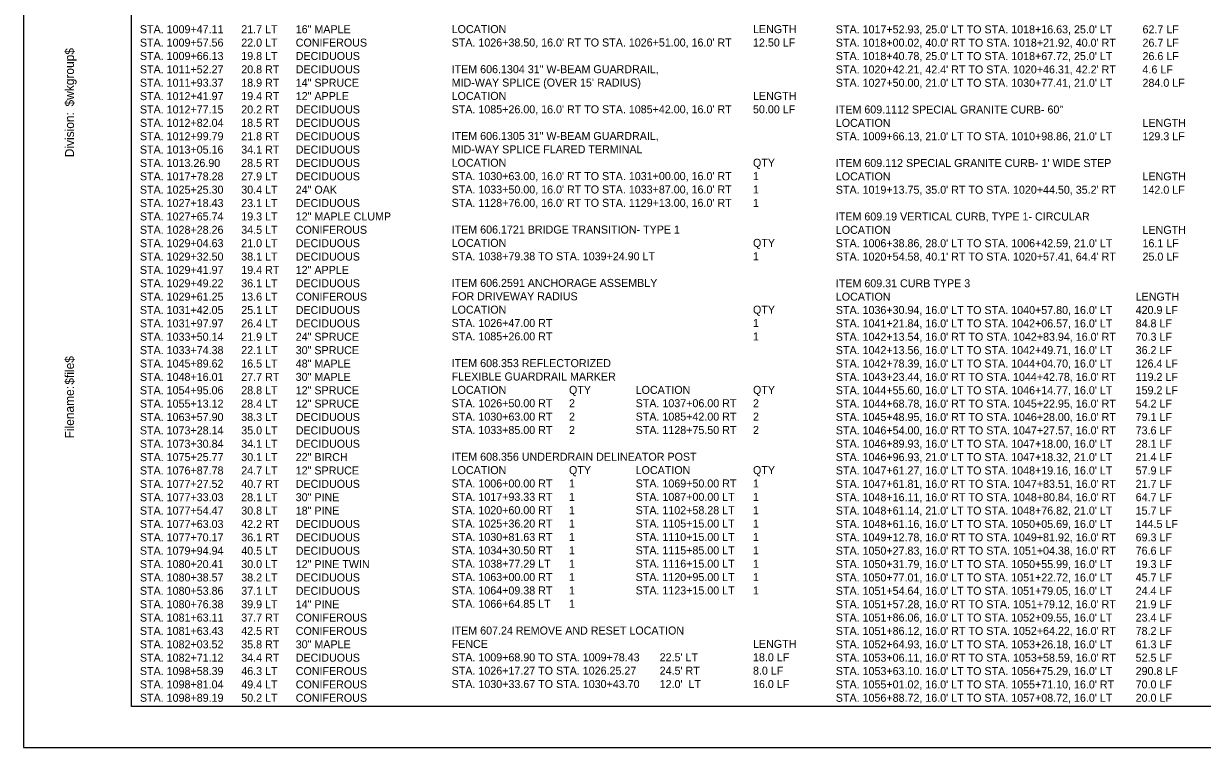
# Model space of a CAD drawing. Extents: x -831 to 3331, y -1004 to 250.
# Drawn here: x 102.6 to 544.6, y -965.1 to -693.8 of the extents above; entities that cross this region are included whole.
import ezdxf

# ---------------------------------------------------------------- set-up
doc = ezdxf.new("R2010")
doc.units = 0
for name, color, linetype in [('BORDER', 7, 'Continuous'), ('Default', 7, 'Continuous'), ('PLOT BOUNDARY', 7, 'Continuous')]:
    doc.layers.add(name, color=color, linetype=linetype)

msp = doc.modelspace()

# ---------------------------------------------------------------- linework, layer by layer
at = {"layer": 'BORDER'}
msp.add_lwpolyline([(143.03, -424.76), (943.03, -424.76), (943.03, -949.76), (143.03, -949.76)], close=True, dxfattribs=at)
at = {"layer": 'PLOT BOUNDARY'}
msp.add_lwpolyline([(102.57, -965.05), (952.57, -965.05), (952.57, -415.05), (102.57, -415.05)], close=True, dxfattribs=at)

# ---------------------------------------------------------------- texts
at = {"layer": 'BORDER'}
for s, p in [('$wkgroup$', (121.46, -724.91)), ('Division:', (121.46, -743.93)), ('$file$', (121.46, -829.13)), ('Filename:', (121.46, -849.27))]:
    msp.add_text(s, height=3.348, rotation=90, dxfattribs=at).set_placement(p)
at = {"layer": 'Default'}
for s, p in [('STA. 1009+47.11', (146.19, -697.46)), ('21.7 LT', (184.19, -697.46)), ('16" MAPLE', (204.62, -697.46)), ('LOCATION', (263.08, -697.42)), ('LENGTH', (376.08, -697.42)), ("STA. 1017+52.93, 25.0' LT TO STA. 1018+16.63, 25.0' LT", (407.14, -697.5)), ('62.7 LF', (522.14, -697.5)), ('STA. 1009+57.56', (146.19, -702.47)), ('22.0 LT', (184.19, -702.47)), ('CONIFEROUS', (204.62, -702.47)), ("STA. 1026+38.50, 16.0' RT TO STA. 1026+51.00, 16.0' RT", (263.08, -702.43)), ('12.50 LF', (376.08, -702.43)), ("STA. 1018+00.02, 40.0' RT TO STA. 1018+21.92, 40.0' RT", (407.14, -702.51)), ('26.7 LF', (522.14, -702.51)), ('STA. 1009+66.13', (146.19, -707.48)), ('19.8 LT', (184.19, -707.48)), ('DECIDUOUS', (204.62, -707.48)), ("STA. 1018+40.78, 25.0' LT TO STA. 1018+67.72, 25.0' LT ", (407.14, -707.52)), ('26.6 LF', (522.14, -707.52)), ('STA. 1011+52.27', (146.19, -712.49)), ('20.8 RT', (184.19, -712.49)), ('DECIDUOUS', (204.62, -712.49)), ('ITEM 606.1304 31" W-BEAM GUARDRAIL, ', (263.08, -712.43)), ("STA. 1020+42.21, 42.4' RT TO STA. 1020+46.31, 42.2' RT", (407.14, -712.53)), ('4.6 LF', (522.14, -712.53)), ('STA. 1011+93.37', (146.19, -717.5)), ('18.9 RT', (184.19, -717.5)), ('14" SPRUCE', (204.62, -717.5)), ("MID-WAY SPLICE (OVER 15' RADIUS)", (263.08, -717.44)), ("STA. 1027+50.00, 21.0' LT TO STA. 1030+77.41, 21.0' LT", (407.14, -717.54)), ('284.0 LF', (522.14, -717.54)), ('STA. 1012+41.97', (146.19, -722.51)), ('19.4 RT', (184.19, -722.51)), ('12" APPLE', (204.62, -722.51)), ('LOCATION', (263.08, -722.45)), ('LENGTH', (376.08, -722.45)), ('STA. 1012+77.15', (146.19, -727.52)), ('20.2 RT', (184.19, -727.52)), ('DECIDUOUS', (204.62, -727.52)), ("STA. 1085+26.00, 16.0' RT TO STA. 1085+42.00, 16.0' RT", (263.08, -727.46)), ('50.00 LF', (376.08, -727.46)), ('ITEM 609.1112 SPECIAL GRANITE CURB- 60"', (407.14, -727.54)), ('STA. 1012+82.04', (146.19, -732.53)), ('18.5 RT', (184.19, -732.53)), ('DECIDUOUS', (204.62, -732.53)), ('LOCATION', (407.14, -732.55)), ('LENGTH', (522.14, -732.55)), ('STA. 1012+99.79', (146.19, -737.54)), ('21.8 RT', (184.19, -737.54)), ('DECIDUOUS', (204.62, -737.54)), ('ITEM 606.1305 31" W-BEAM GUARDRAIL, ', (263.08, -737.46)), ("STA. 1009+66.13, 21.0' LT TO STA. 1010+98.86, 21.0' LT", (407.14, -737.56)), ('129.3 LF', (522.14, -737.56)), ('STA. 1013+05.16', (146.19, -742.55)), ('34.1 RT', (184.19, -742.55)), ('DECIDUOUS', (204.62, -742.55)), ('MID-WAY SPLICE FLARED TERMINAL', (263.08, -742.47)), ('STA. 1013.26.90', (146.19, -747.56)), ('28.5 RT', (184.19, -747.56)), ('DECIDUOUS', (204.62, -747.56)), ('LOCATION', (263.08, -747.48)), ('QTY', (376.08, -747.48)), ("ITEM 609.112 SPECIAL GRANITE CURB- 1' WIDE STEP", (407.14, -747.58)), ('STA. 1017+78.28', (146.19, -752.57)), ('27.9 LT', (184.19, -752.57)), ('DECIDUOUS', (204.62, -752.57)), ("STA. 1030+63.00, 16.0' RT TO STA. 1031+00.00, 16.0' RT", (263.08, -752.49)), ('1', (376.08, -752.49)), ('LOCATION', (407.14, -752.59)), ('LENGTH', (522.14, -752.59)), ('STA. 1025+25.30', (146.19, -757.58)), ('30.4 LT', (184.19, -757.58)), ('24" OAK', (204.62, -757.58)), ("STA. 1033+50.00, 16.0' RT TO STA. 1033+87.00, 16.0' RT", (263.08, -757.5)), ('1', (376.08, -757.5)), ("STA. 1019+13.75, 35.0' RT TO STA. 1020+44.50, 35.2' RT", (407.14, -757.6)), ('142.0 LF', (522.14, -757.6)), ('STA. 1027+18.43', (146.19, -762.59)), ('23.1 LT', (184.19, -762.59)), ('DECIDUOUS', (204.62, -762.59)), ("STA. 1128+76.00, 16.0' RT TO STA. 1129+13.00, 16.0' RT", (263.08, -762.51)), ('1', (376.08, -762.51)), ('STA. 1027+65.74', (146.19, -767.6)), ('19.3 LT', (184.19, -767.6)), ('12" MAPLE CLUMP', (204.62, -767.6)), ('ITEM 609.19 VERTICAL CURB, TYPE 1- CIRCULAR', (407.14, -767.62)), ('STA. 1028+28.26', (146.19, -772.61)), ('34.5 LT', (184.19, -772.61)), ('CONIFEROUS', (204.62, -772.61)), ('ITEM 606.1721 BRIDGE TRANSITION- TYPE 1', (263.08, -772.51)), ('LOCATION', (407.14, -772.63)), ('LENGTH', (522.14, -772.63)), ('STA. 1029+04.63', (146.19, -777.62)), ('21.0 LT', (184.19, -777.62)), ('DECIDUOUS', (204.62, -777.62)), ('LOCATION', (263.08, -777.52)), ('QTY', (376.08, -777.52)), ("STA. 1006+38.86, 28.0' LT TO STA. 1006+42.59, 21.0' LT", (407.14, -777.64)), ('16.1 LF', (522.14, -777.64)), ('STA. 1029+32.50', (146.19, -782.63)), ('38.1 LT', (184.19, -782.63)), ('DECIDUOUS', (204.62, -782.63)), ('STA. 1038+79.38 TO STA. 1039+24.90 LT', (263.08, -782.53)), ('1', (376.08, -782.53)), ("STA. 1020+54.58, 40.1' RT TO STA. 1020+57.41, 64.4' RT", (407.14, -782.65)), ('25.0 LF', (522.14, -782.65)), ('STA. 1029+41.97', (146.19, -787.64)), ('19.4 RT', (184.19, -787.64)), ('12" APPLE', (204.62, -787.64)), ('STA. 1029+49.22', (146.19, -792.65)), ('36.1 LT', (184.19, -792.65)), ('DECIDUOUS', (204.62, -792.65)), ('ITEM 606.2591 ANCHORAGE ASSEMBLY', (263.08, -792.51)), ('ITEM 609.31 CURB TYPE 3', (407.14, -792.65)), ('STA. 1029+61.25', (146.19, -797.66)), ('13.6 LT', (184.19, -797.66)), ('CONIFEROUS', (204.62, -797.66)), ('FOR DRIVEWAY RADIUS', (263.08, -797.52)), ('LOCATION', (407.14, -797.66)), ('LENGTH', (519.57, -797.66)), ('STA. 1031+42.05', (146.19, -802.67)), ('25.1 LT', (184.19, -802.67)), ('DECIDUOUS', (204.62, -802.67)), ('LOCATION', (263.08, -802.53)), ('QTY', (376.08, -802.53)), ("STA. 1036+30.94, 16.0' LT TO STA. 1040+57.80, 16.0' LT", (407.14, -802.67)), ('420.9 LF', (519.57, -802.67)), ('STA. 1026+47.00 RT', (263.08, -807.54)), ('STA. 1031+97.97', (146.19, -807.68)), ('26.4 LT', (184.19, -807.68)), ('DECIDUOUS', (204.62, -807.68)), ('1', (376.08, -807.54)), ("STA. 1041+21.84, 16.0' LT TO STA. 1042+06.57, 16.0' LT", (407.14, -807.68)), ('84.8 LF', (519.57, -807.68)), ('STA. 1033+50.14', (146.19, -812.69)), ('21.9 LT', (184.19, -812.69)), ('24" SPRUCE', (204.62, -812.69)), ('STA. 1085+26.00 RT', (263.08, -812.55)), ('1', (376.08, -812.55)), ("STA. 1042+13.54, 16.0' RT TO STA. 1042+83.94, 16.0' RT", (407.14, -812.69)), ('70.3 LF', (519.57, -812.69)), ('STA. 1033+74.38', (146.19, -817.7)), ('22.1 LT', (184.19, -817.7)), ('30" SPRUCE', (204.62, -817.7)), ("STA. 1042+13.56, 16.0' LT TO STA. 1042+49.71, 16.0' LT", (407.14, -817.7)), ('36.2 LF', (519.57, -817.7)), ('STA. 1045+89.62', (146.19, -822.71)), ('16.5 LT', (184.19, -822.71)), ('48" MAPLE', (204.62, -822.71)), ('ITEM 608.353 REFLECTORIZED ', (263.08, -822.57)), ("STA. 1042+78.39, 16.0' LT TO STA. 1044+04.70, 16.0' LT", (407.14, -822.71)), ('126.4 LF', (519.57, -822.71)), ('STA. 1048+16.01', (146.19, -827.72)), ('27.7 RT', (184.19, -827.72)), ('30" MAPLE', (204.62, -827.72)), ('FLEXIBLE GUARDRAIL MARKER', (263.08, -827.58)), ("STA. 1043+23.44, 16.0' RT TO STA. 1044+42.78, 16.0' RT", (407.14, -827.72)), ('119.2 LF', (519.57, -827.72)), ('STA. 1054+95.06', (146.19, -832.73)), ('28.8 LT', (184.19, -832.73)), ('12" SPRUCE', (204.62, -832.73)), ('LOCATION', (263.08, -832.59)), ('QTY', (307.08, -832.59)), ('LOCATION', (332.08, -832.59)), ('QTY', (376.08, -832.59)), ("STA. 1044+55.60, 16.0' LT TO STA. 1046+14.77, 16.0' LT", (407.14, -832.73)), ('159.2 LF', (519.57, -832.73)), ('STA. 1055+13.12', (146.19, -837.74)), ('28.4 LT', (184.19, -837.74)), ('12" SPRUCE', (204.62, -837.74)), ('STA. 1026+50.00 RT', (263.08, -837.6)), ('2', (307.08, -837.6)), ('STA. 1037+06.00 RT', (332.08, -837.6)), ('2', (376.08, -837.6)), ("STA. 1044+68.78, 16.0' RT TO STA. 1045+22.95, 16.0' RT", (407.14, -837.74)), ('54.2 LF', (519.57, -837.74)), ('STA. 1063+57.90', (146.19, -842.75)), ('38.3 LT', (184.19, -842.75)), ('DECIDUOUS', (204.62, -842.75)), ('STA. 1030+63.00 RT', (263.08, -842.61)), ('2', (307.08, -842.61)), ('STA. 1085+42.00 RT', (332.08, -842.61)), ('2', (376.08, -842.61)), ("STA. 1045+48.95, 16.0' RT TO STA. 1046+28.00, 16.0' RT", (407.14, -842.75)), ('79.1 LF', (519.57, -842.75)), ('STA. 1073+28.14', (146.19, -847.76)), ('35.0 LT', (184.19, -847.76)), ('DECIDUOUS', (204.62, -847.76)), ('STA. 1033+85.00 RT', (263.08, -847.62)), ('2', (307.08, -847.62)), ('STA. 1128+75.50 RT', (332.08, -847.62)), ('2', (376.08, -847.62)), ("STA. 1046+54.00, 16.0' RT TO STA. 1047+27.57, 16.0' RT", (407.14, -847.76)), ('73.6 LF', (519.57, -847.76)), ('STA. 1073+30.84', (146.19, -852.77)), ('34.1 LT', (184.19, -852.77)), ('DECIDUOUS', (204.62, -852.77)), ("STA. 1046+89.93, 16.0' LT TO STA. 1047+18.00, 16.0' LT", (407.14, -852.77)), ('28.1 LF', (519.57, -852.77)), ('STA. 1075+25.77', (146.19, -857.78)), ('30.1 LT', (184.19, -857.78)), ('22" BIRCH', (204.62, -857.78)), ('ITEM 608.356 UNDERDRAIN DELINEATOR POST', (263.08, -857.64)), ("STA. 1046+96.93, 21.0' LT TO STA. 1047+18.32, 21.0' LT", (407.14, -857.78)), ('21.4 LF', (519.57, -857.78)), ('STA. 1076+87.78', (146.19, -862.79)), ('24.7 LT', (184.19, -862.79)), ('12" SPRUCE', (204.62, -862.79)), ('LOCATION', (263.08, -862.65)), ('QTY', (307.08, -862.65)), ('LOCATION', (332.08, -862.65)), ('QTY', (376.08, -862.65)), ("STA. 1047+61.27, 16.0' LT TO STA. 1048+19.16, 16.0' LT", (407.14, -862.79)), ('57.9 LF', (519.57, -862.79)), ('STA. 1077+27.52', (146.19, -867.8)), ('40.7 RT', (184.19, -867.8)), ('DECIDUOUS', (204.62, -867.8)), ('STA. 1006+00.00 RT', (263.08, -867.66)), ('1', (307.08, -867.66)), ('STA. 1069+50.00 RT', (332.08, -867.66)), ('1', (376.08, -867.66)), ("STA. 1047+61.81, 16.0' RT TO STA. 1047+83.51, 16.0' RT", (407.14, -867.8)), ('21.7 LF', (519.57, -867.8)), ('STA. 1077+33.03', (146.19, -872.81)), ('28.1 LT', (184.19, -872.81)), ('30" PINE', (204.62, -872.81)), ('STA. 1017+93.33 RT', (263.08, -872.67)), ('1', (307.08, -872.67)), ('STA. 1087+00.00 LT', (332.08, -872.67)), ('1', (376.08, -872.67)), ("STA. 1048+16.11, 16.0' RT TO STA. 1048+80.84, 16.0' RT", (407.14, -872.81)), ('64.7 LF', (519.57, -872.81)), ('STA. 1077+54.47', (146.19, -877.82)), ('30.8 LT', (184.19, -877.82)), ('18" PINE', (204.62, -877.82)), ('STA. 1020+60.00 RT', (263.08, -877.68)), ('1', (307.08, -877.68)), ('STA. 1102+58.28 LT', (332.08, -877.68)), ('1', (376.08, -877.68)), ("STA. 1048+61.14, 21.0' LT TO STA. 1048+76.82, 21.0' LT", (407.14, -877.82)), ('15.7 LF', (519.57, -877.82)), ('STA. 1025+36.20 RT', (263.08, -882.69)), ('STA. 1105+15.00 LT', (332.08, -882.69)), ('STA. 1077+63.03', (146.19, -882.83)), ('42.2 RT', (184.19, -882.83)), ('DECIDUOUS', (204.62, -882.83)), ('1', (307.08, -882.69)), ('1', (376.08, -882.69)), ("STA. 1048+61.16, 16.0' LT TO STA. 1050+05.69, 16.0' LT", (407.14, -882.83)), ('144.5 LF', (519.57, -882.83)), ('STA. 1077+70.17', (146.19, -887.84)), ('36.1 RT', (184.19, -887.84)), ('DECIDUOUS', (204.62, -887.84)), ('STA. 1030+81.63 RT', (263.08, -887.7)), ('1', (307.08, -887.7)), ('STA. 1110+15.00 LT', (332.08, -887.7)), ('1', (376.08, -887.7)), ("STA. 1049+12.78, 16.0' RT TO STA. 1049+81.92, 16.0' RT", (407.14, -887.84)), ('69.3 LF', (519.57, -887.84)), ('STA. 1079+94.94', (146.19, -892.85)), ('40.5 LT', (184.19, -892.85)), ('DECIDUOUS', (204.62, -892.85)), ('STA. 1034+30.50 RT', (263.08, -892.71)), ('1', (307.08, -892.71)), ('STA. 1115+85.00 LT', (332.08, -892.71)), ('1', (376.08, -892.71)), ("STA. 1050+27.83, 16.0' RT TO STA. 1051+04.38, 16.0' RT", (407.14, -892.85)), ('76.6 LF', (519.57, -892.85)), ('STA. 1080+20.41', (146.19, -897.86)), ('30.0 LT', (184.19, -897.86)), ('12" PINE TWIN', (204.62, -897.86)), ('STA. 1038+77.29 LT', (263.08, -897.72)), ('1', (307.08, -897.72)), ('STA. 1116+15.00 LT', (332.08, -897.72)), ('1', (376.08, -897.72)), ("STA. 1050+31.79, 16.0' LT TO STA. 1050+55.99, 16.0' LT", (407.14, -897.86)), ('19.3 LF', (519.57, -897.86)), ('STA. 1080+38.57', (146.19, -902.87)), ('38.2 LT', (184.19, -902.87)), ('DECIDUOUS', (204.62, -902.87)), ('STA. 1063+00.00 RT', (263.08, -902.73)), ('1', (307.08, -902.73)), ('STA. 1120+95.00 LT', (332.08, -902.73)), ('1', (376.08, -902.73)), ("STA. 1050+77.01, 16.0' LT TO STA. 1051+22.72, 16.0' LT", (407.14, -902.87)), ('45.7 LF', (519.57, -902.87)), ('STA. 1080+53.86', (146.19, -907.88)), ('37.1 LT', (184.19, -907.88)), ('DECIDUOUS', (204.62, -907.88)), ('STA. 1064+09.38 RT', (263.08, -907.74)), ('1', (307.08, -907.74)), ('STA. 1123+15.00 LT', (332.08, -907.74)), ('1', (376.08, -907.74)), ("STA. 1051+54.64, 16.0' LT TO STA. 1051+79.05, 16.0' LT", (407.14, -907.88)), ('24.4 LF', (519.57, -907.88)), ('STA. 1080+76.38', (146.19, -912.89)), ('39.9 LT', (184.19, -912.89)), ('14" PINE', (204.62, -912.89)), ('STA. 1066+64.85 LT', (263.08, -912.75)), ('1', (307.08, -912.75)), ("STA. 1051+57.28, 16.0' RT TO STA. 1051+79.12, 16.0' RT", (407.14, -912.89)), ('21.9 LF', (519.57, -912.89)), ('STA. 1081+63.11', (146.19, -917.9)), ('37.7 RT', (184.19, -917.9)), ('CONIFEROUS', (204.62, -917.9)), ("STA. 1051+86.06, 16.0' LT TO STA. 1052+09.55, 16.0' LT", (407.14, -917.9)), ('23.4 LF', (519.57, -917.9)), ('STA. 1081+63.43', (146.19, -922.91)), ('42.5 RT', (184.19, -922.91)), ('CONIFEROUS', (204.62, -922.91)), ('ITEM 607.24 REMOVE AND RESET LOCATION', (263.08, -922.77)), ("STA. 1051+86.12, 16.0' RT TO STA. 1052+64.22, 16.0' RT", (407.14, -922.91)), ('78.2 LF', (519.57, -922.91)), ('STA. 1082+03.52', (146.19, -927.92)), ('35.8 RT', (184.19, -927.92)), ('30" MAPLE', (204.62, -927.92)), ('FENCE', (263.08, -927.78)), ('LENGTH', (376.08, -927.78)), ("STA. 1052+64.93, 16.0' LT TO STA. 1053+26.18, 16.0' LT", (407.14, -927.92)), ('61.3 LF', (519.57, -927.92)), ('STA. 1082+71.12', (146.19, -932.93)), ('34.4 RT', (184.19, -932.93)), ('DECIDUOUS', (204.62, -932.93)), ('STA. 1009+68.90 TO STA. 1009+78.43', (263.08, -932.79)), ("22.5' LT", (341.08, -932.79)), ('18.0 LF', (376.08, -932.79)), ("STA. 1053+06.11, 16.0' RT TO STA. 1053+58.59, 16.0' RT", (407.14, -932.93)), ('52.5 LF', (519.57, -932.93)), ('STA. 1098+58.39', (146.19, -937.94)), ('46.3 LT', (184.19, -937.94)), ('CONIFEROUS', (204.62, -937.94)), ('STA. 1026+17.27 TO STA. 1026.25.27', (263.08, -937.8)), ("24.5' RT", (341.08, -937.8)), ('8.0 LF', (376.08, -937.8)), ("STA. 1053+63.10. 16.0' LT TO STA. 1056+75.29, 16.0' LT", (407.14, -937.94)), ('290.8 LF', (519.57, -937.94)), ('STA. 1098+81.04', (146.19, -942.95)), ('49.4 LT', (184.19, -942.95)), ('CONIFEROUS', (204.62, -942.95)), ('STA. 1030+33.67 TO STA. 1030+43.70', (263.08, -942.81)), ("12.0'  LT", (341.08, -942.81)), ('16.0 LF', (376.08, -942.81)), ("STA. 1055+01.02, 16.0' LT TO STA. 1055+71.10, 16.0' RT", (407.14, -942.95)), ('70.0 LF', (519.57, -942.95)), ('STA. 1098+89.19', (146.19, -947.96)), ('50.2 LT', (184.19, -947.96)), ('CONIFEROUS', (204.62, -947.96)), ("STA. 1056+88.72, 16.0' LT TO STA. 1057+08.72, 16.0' LT", (407.14, -947.96)), ('20.0 LF', (519.57, -947.96))]:
    msp.add_text(s, height=3, dxfattribs=at).set_placement(p)

doc.saveas('drawing.dxf')
